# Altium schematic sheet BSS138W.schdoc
size 127 x 101 mm
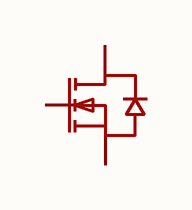
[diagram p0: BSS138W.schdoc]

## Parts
Q?  bss138w_c504052  [SOT-323-3_L2.0-W1.3-P1.30-LS2.1-BR]  (value not drawn)

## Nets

Not connected (* = marked no-connect by the designer): Q? 1(G) 2(S) 3(D)

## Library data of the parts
Q? = bss138w_c504052: 数量:1个N沟道;漏源电压(Vdss):50V;连续漏极电流(Id):220mA;导通电阻(RDS(on)):6Ω@4.5V;耗散功率(Pd):300mW;阈值电压(Vgs(th)):1.5V;; Manufacturer: CJ(江苏长电/长晶); AddInBom: yes; ModelId: 59529c0d6fc749f28f2d0659e12986b4; ModelName: SOT-323-3_L2.0-W1.3-H1.0-LS2.1-P1.30; ModelTransform: 78.74,82.677,0,90,0,0,0.0005,0,0; Number: 1个N沟道; Drain to Source Voltage: 50V; Current - Continuous Drain(Id): 220mA; Pd - Power Dissipation: 300mW; Gate Threshold Voltage (Vgs(th)): 1.5V; Input Capacitance(Ciss): 27pF; Reverse Transfer Capacitance (Crss@Vds): 6pF; Type: N沟道; Output Capacitance(Coss): 13pF; Vgs: ±20V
